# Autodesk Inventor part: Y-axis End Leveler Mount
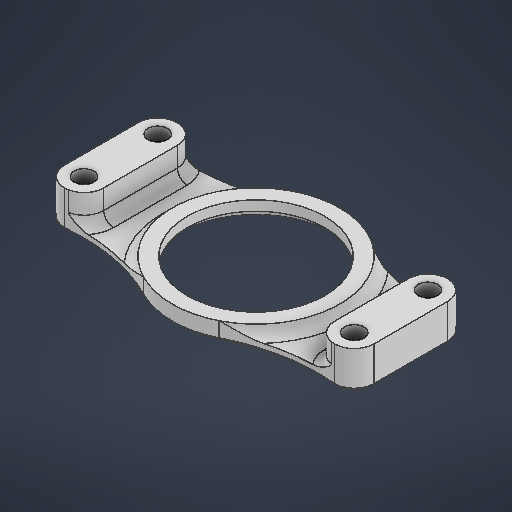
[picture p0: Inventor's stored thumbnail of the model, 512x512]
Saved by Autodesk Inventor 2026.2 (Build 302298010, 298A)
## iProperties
Created: 2026-04
Part Number: Y-axis End Leveler Mount
Material: 일반
Document SubType Name: Modeling
Designer: work
Density: 1 g/cm^3
Appearance: 기본값
Author: work
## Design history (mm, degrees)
sketch "스케치1"
  geometry: L1 (27.5, 7.5)-(27.5, -7.5); L2 (27.5, 0)-(0, 0); L3 (0, 17)-(0, -17); L4 (27.5, 7.5)-(27.5, -7.5); L5 (23.5, 7.5)-(23.5, -7.5); L6 (31.5, -7.5)-(31.5, 7.5); L7 (-27.5, 0)-(0, 0); L8 (-31.5, -7.5)-(-31.5, 7.5); L9 (-27.5, 7.5)-(-27.5, -7.5); L10 (-27.5, 7.5)-(-27.5, -7.5); L11 (-23.5, 7.5)-(-23.5, -7.5); C1 r 2 at (27.5, 7.5); C2 r 2 at (27.5, -7.5); C3 r 2 at (-27.5, -7.5); C4 r 2 at (-27.5, 7.5); C5 r 16 at (0, 0); C6 r 14 at (0, 0); A1 r 17 centre (0, 0) between (0, 17) and (0, -17); A2 r 4 centre (27.5, 7.5) between (31.5, 7.5) and (23.5, 7.5); A3 r 4 centre (27.5, -7.5) between (23.5, -7.5) and (31.5, -7.5); A4 r 36 centre (23.876, 47.317) between (7.658, 15.177) and (27.5, 11.5); A5 r 36 centre (23.876, -47.317) between (27.5, -11.5) and (7.658, -15.177); A6 r 4 centre (-27.5, -7.5) between (-31.5, -7.5) and (-23.5, -7.5); A7 r 36 centre (-23.876, -47.317) between (-7.658, -15.177) and (-27.5, -11.5); A8 r 4 centre (-27.5, 7.5) between (-23.5, 7.5) and (-31.5, 7.5); A9 r 36 centre (-23.876, 47.317) between (-27.5, 11.5) and (-7.658, 15.177); 12 further points
  constraints: 26 end point, 20 point on circle, 19 symmetric about line, 15 centre point, 7 coincident, 5 tangent, 3 vertical, 2 midpoint, 1 horizontal, 1 parallel, 7 other
  dimensions: "d0" = 34 diameter of A1; "d1" = 4 diameter of C1; "d2" = 4 diameter of C2; "d3" = 15 distance of L1.start L1.end; "d4" = 28.504 distance of L4.end L2.end; "d5" = 34 distance of L3.start L3.end; "d6" = 4 radius of A3; "d7" = 36 radius of A4; "d8" = 32 diameter of C5; "d9" = 2 radial gap between concentric circles of C6 C5
extrude "돌출1" new body sketch "스케치1" distance "d10" = 2; taper "d11" = 0 deg
extrude "돌출2" join sketch "스케치1" distance "d12" = 8; taper "d13" = 0 deg
extrude "돌출3" join sketch "스케치1" distance "d14" = 2; taper "d15" = 0 deg
sketch "스케치2"
  geometry: L1 (23.5, -7.5)-(23.5, 7.5) reference; L2 (-23.5, 7.5)-(-23.5, -7.5) reference; C1 r 16 at (0, 0) reference; C2 r 14 at (0, 0); C3 r 17 at (0, 0); A1 r 4 centre (-27.5, -7.5) between (-26.778, -11.434) and (-23.5, -7.5) reference; A2 r 36 centre (-23.876, -47.317) between (-7.658, -15.177) and (-26.778, -11.434) reference; A3 r 17 centre (0, 0) between (-7.658, -15.177) and (7.658, -15.177) reference; A4 r 36 centre (23.876, -47.317) between (26.778, -11.434) and (7.658, -15.177) reference; A5 r 4 centre (27.5, -7.5) between (23.5, -7.5) and (26.778, -11.434) reference; A6 r 4 centre (27.5, 7.5) between (26.778, 11.434) and (23.5, 7.5) reference; A7 r 36 centre (23.876, 47.317) between (7.658, 15.177) and (26.778, 11.434) reference; A8 r 17 centre (0, 0) between (7.658, 15.177) and (-7.658, 15.177) reference; A9 r 36 centre (-23.876, 47.317) between (-26.778, 11.434) and (-7.658, 15.177) reference; A10 r 4 centre (-27.5, 7.5) between (-23.5, 7.5) and (-26.778, 11.434) reference; 5 further points
  constraints: 2 centre point, 2 coincident, 1 tangent
  dimensions: "d16" = 2 radial gap between concentric circles of C1 C2
extrude "돌출4" join sketch "스케치2" distance "d17" = 2; taper "d18" = 0 deg
fillet "모깎기1" dims "d19" = 2
chamfer "모따기1" distance "d20" = 1; stored, may be unused: second distance "d21" = 2, angle "d22" = 45 deg
feature "ǚ耀ǜ耀Ǟ耀Ǡ耀Ǣ耀Ǥ耀Ǧ耀Ǩ耀" dims "d0" = 34, "d1" = 4, "d2" = 4, "d3" = 15, "d4" = 28.504, "d5" = 34, "d6" = 4, "d7" = 36, "d8" = 32, "d9" = 2, "d10" = 2, "d11" = 0, "d12" = 8, "d13" = 0, "d14" = 2, "d15" = 0, "d16" = 2, "d17" = 2, "d18" = 0, "d19" = 2, "d20" = 1, "d21" = 2, "d22" = 45 deg
node "솔리드1"
node "투영된 루프1"
